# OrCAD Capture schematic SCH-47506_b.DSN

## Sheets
1 1. Title Page: title: 47506-X-BPMS-SHIELD-BOARD; rev: X1; company: NXP Semiconductors; note: SCH47506, SPF47506
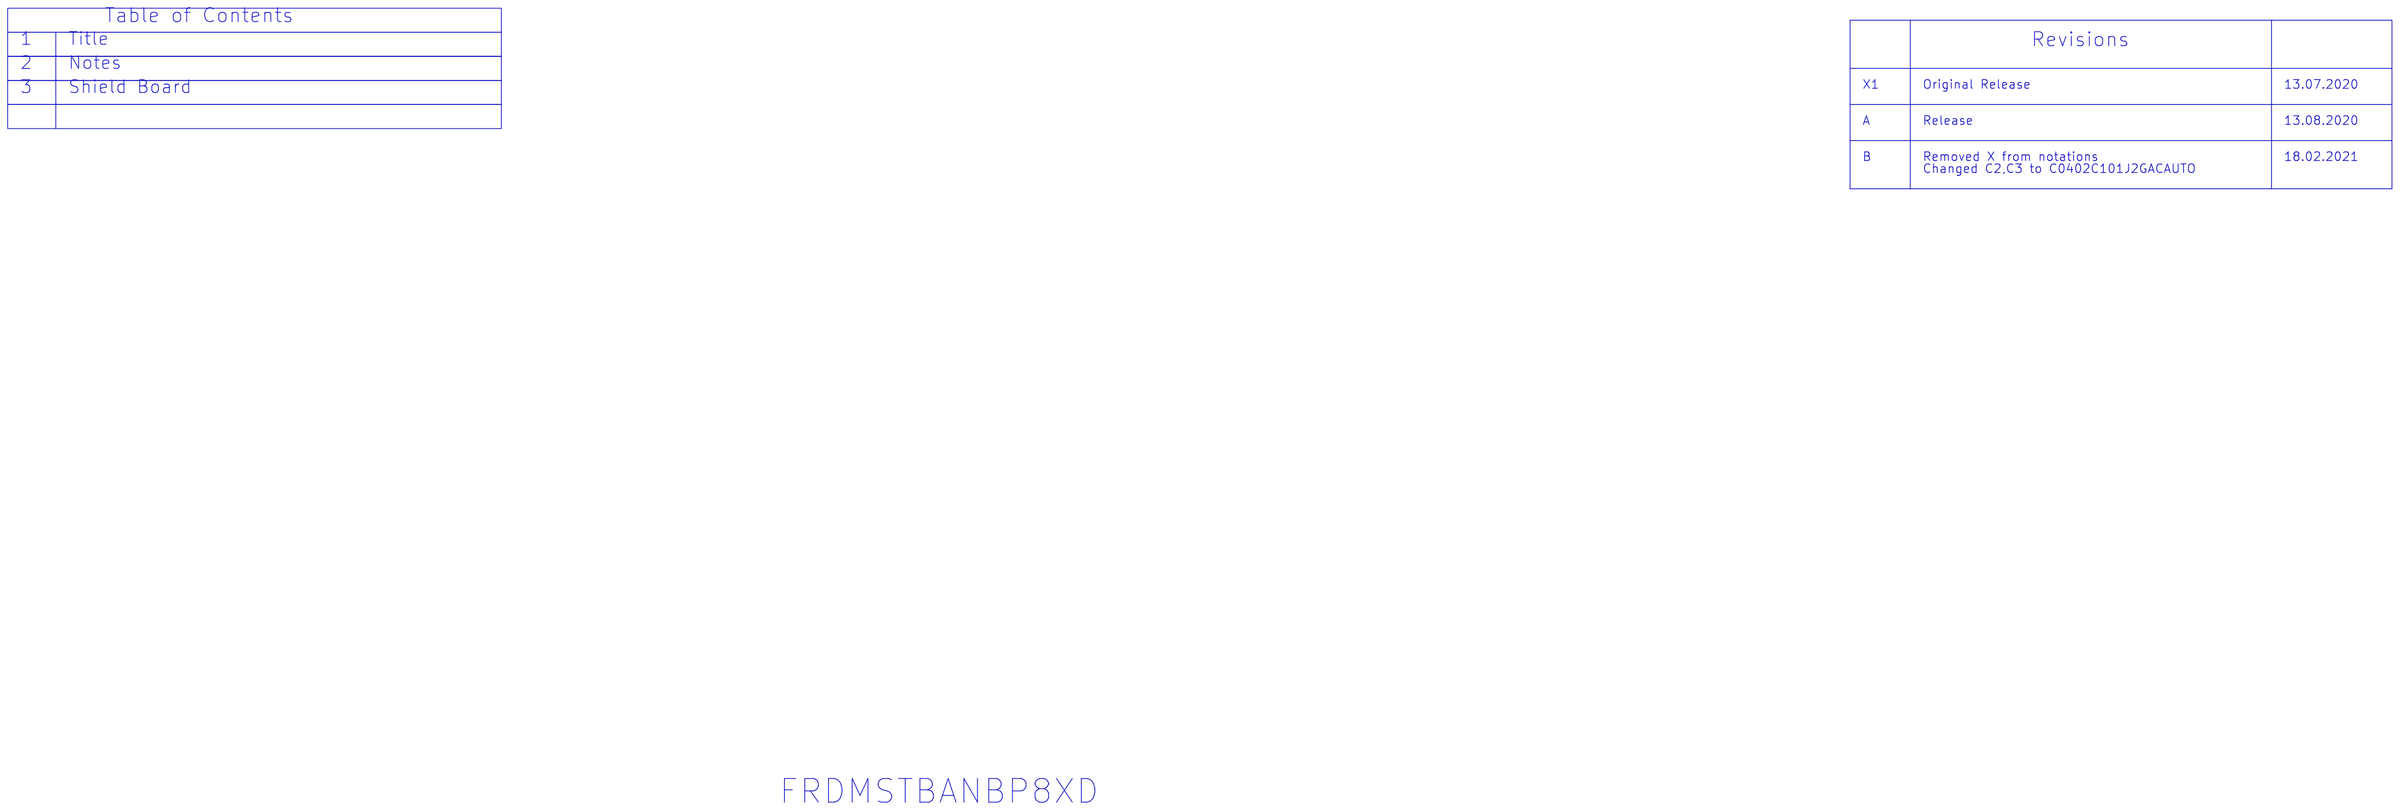
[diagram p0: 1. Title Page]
2 2. Notes
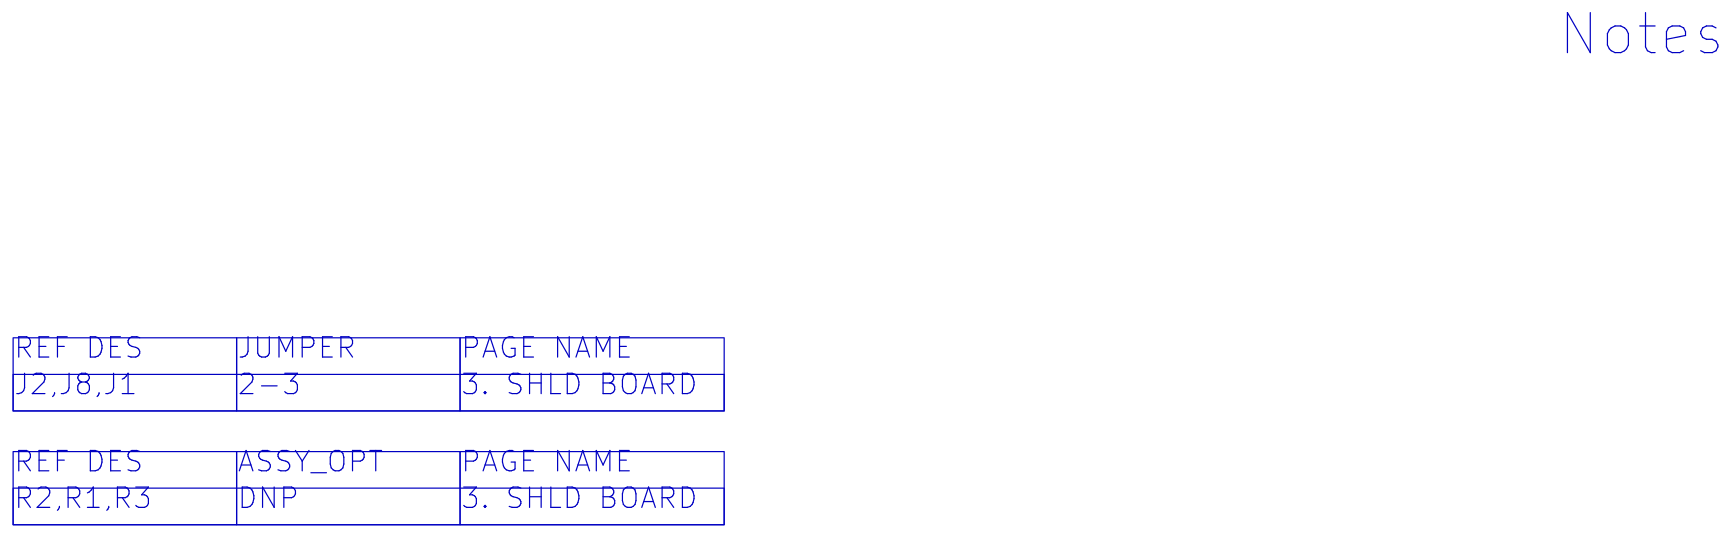
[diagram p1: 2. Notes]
3 3. SHLD BOARD: size C
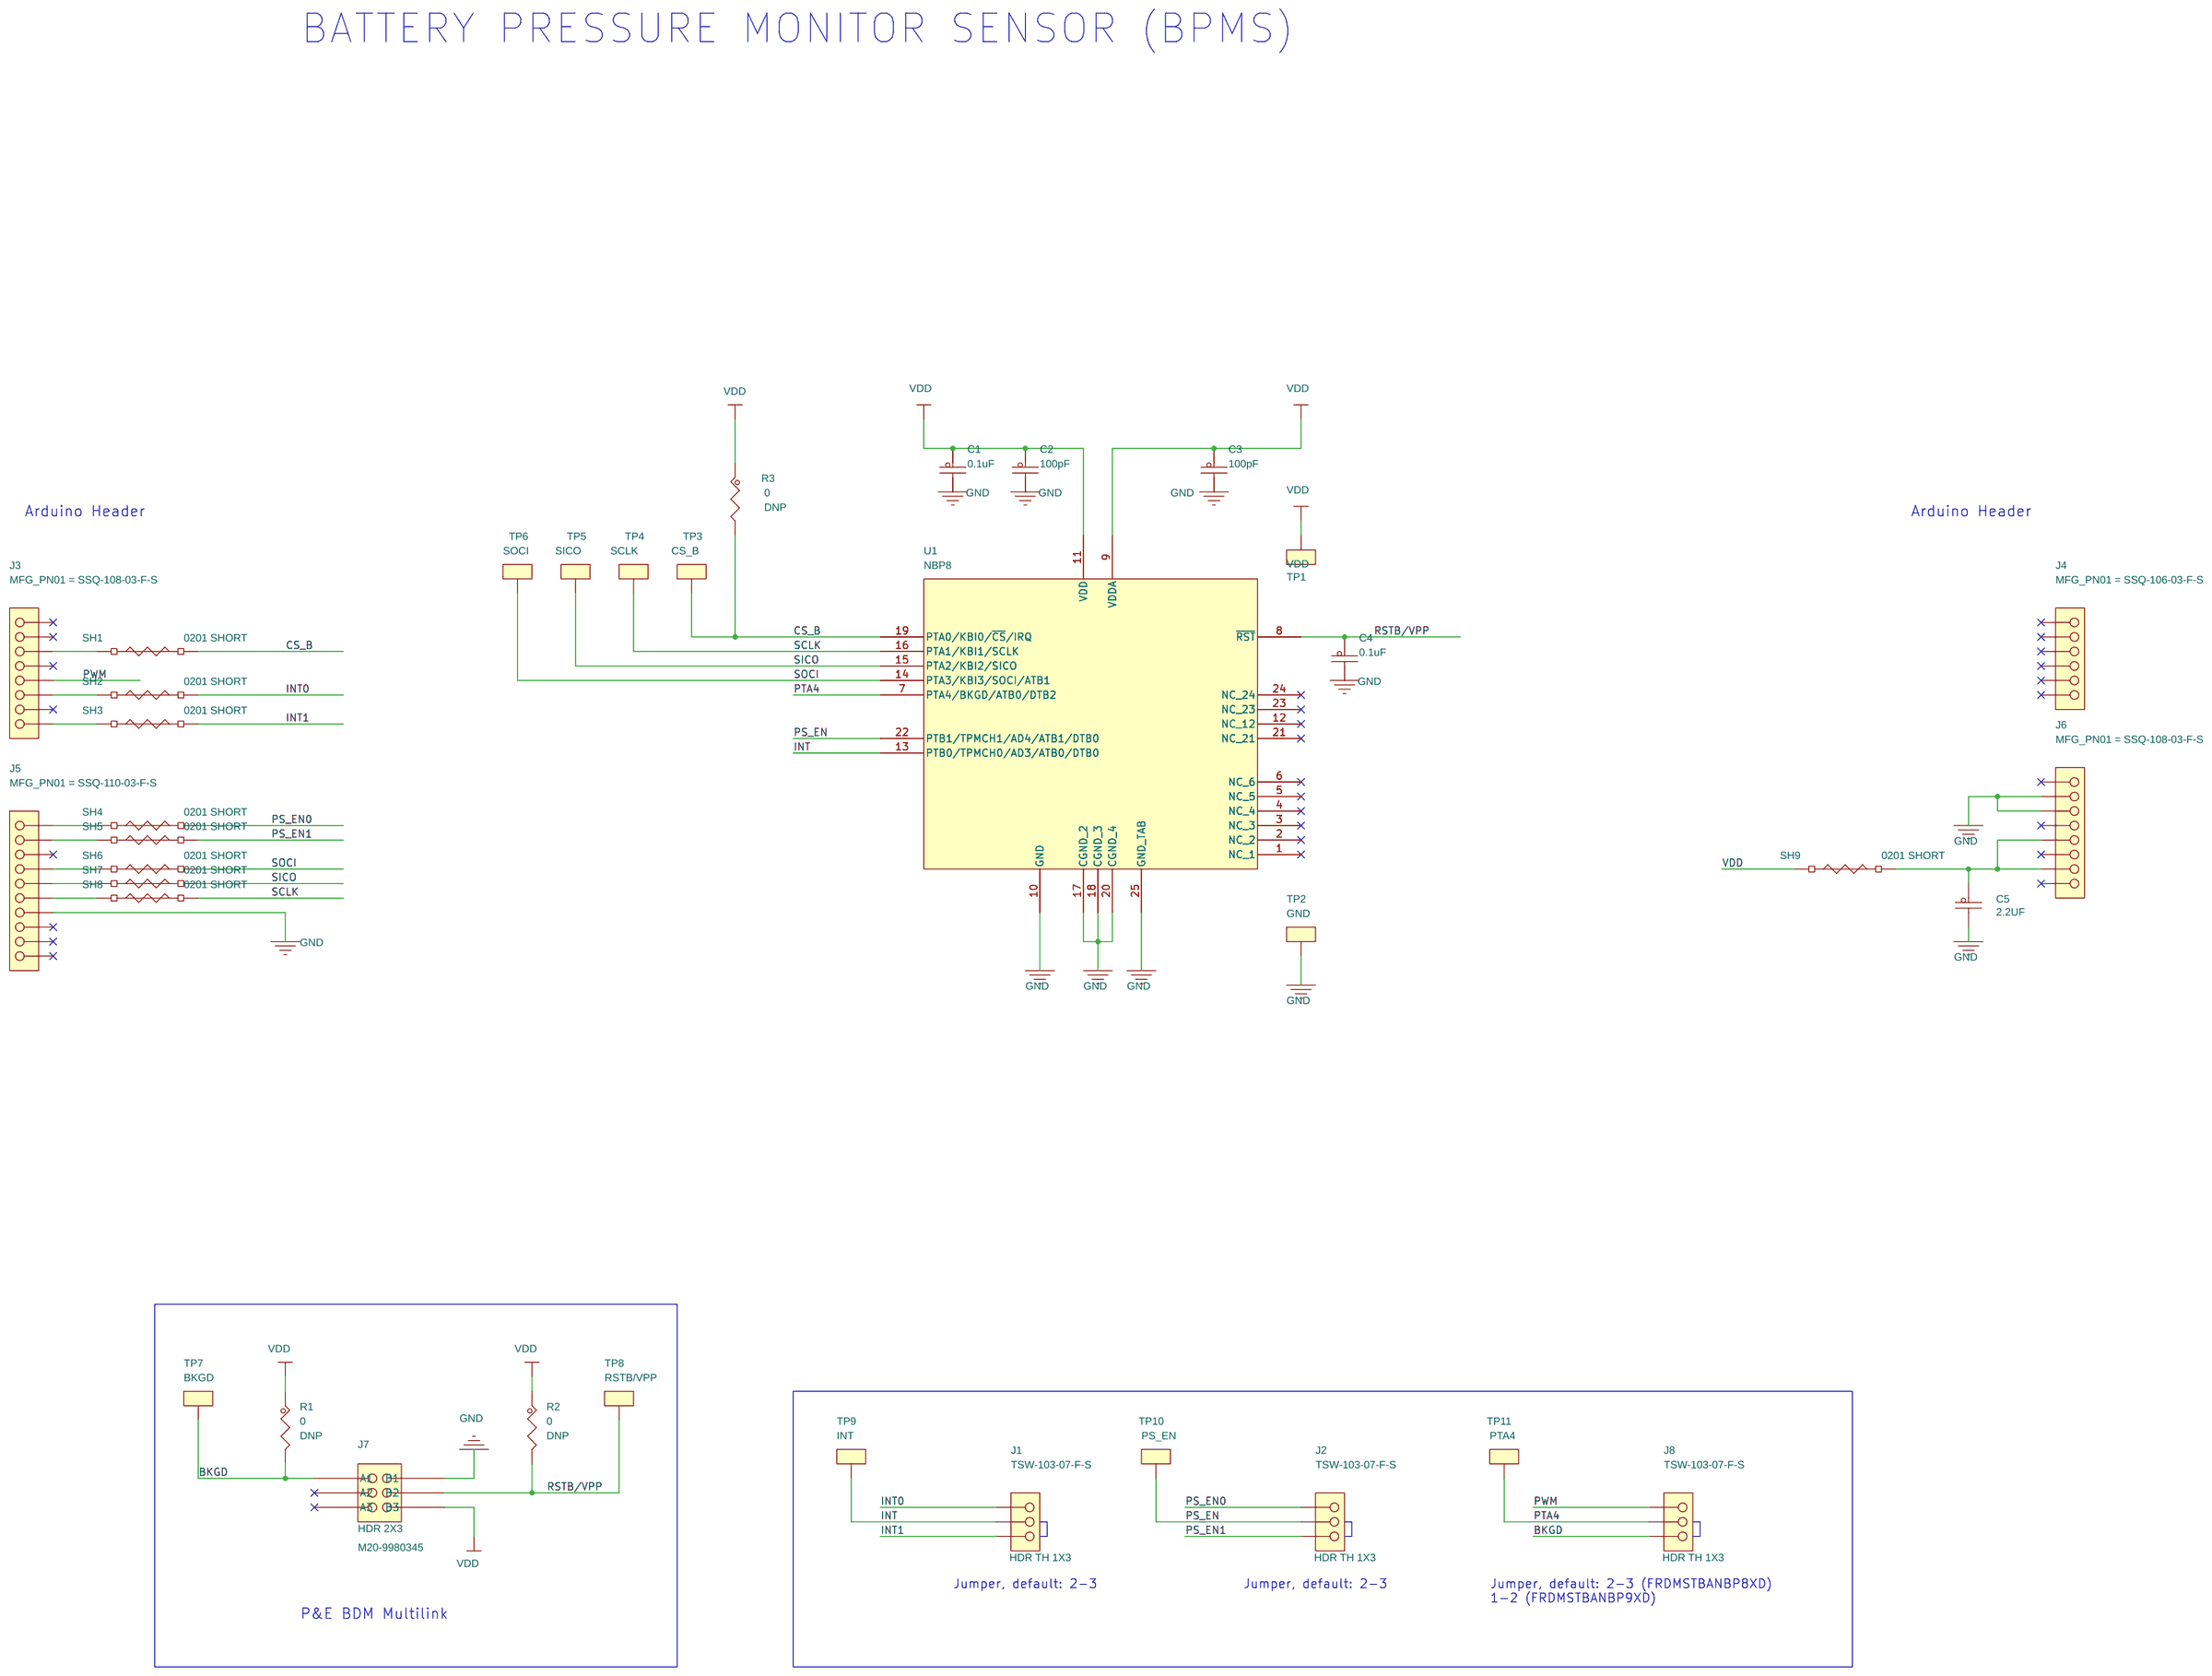
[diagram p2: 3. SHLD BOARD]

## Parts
C1  0.1uF  [CC0402_25]
C2  100pF  [CC0402_25]
C3  100pF  [CC0402_25]
C4  0.1uF  [CC0402_25]
C5  2.2UF  [CC0402_25]
J1  HDR TH 1X3  [HDR103]
J2  HDR TH 1X3  [HDR103]
J3  SKT_1X8  [con_skt1x8_th]
J4  SKT_1X6  [con_skt1x6_th]
J5  SKT_1X10  [con_skt1x10_th]
J6  SKT_1X8  [con_skt1x8_th]
J7  HDR 2X3  [hdr203_m20]
J8  HDR TH 1X3  [HDR103]
R1  0  [RC0402_25]
R2  0  [RC0402_25]
R3  0  [RC0402_25]
SH1  0201 SHORT  [0201_solder_blob_jumper_short]
SH2  0201 SHORT  [0201_solder_blob_jumper_short]
SH3  0201 SHORT  [0201_solder_blob_jumper_short]
SH4  0201 SHORT  [0201_solder_blob_jumper_short]
SH5  0201 SHORT  [0201_solder_blob_jumper_short]
SH6  0201 SHORT  [0201_solder_blob_jumper_short]
SH7  0201 SHORT  [0201_solder_blob_jumper_short]
SH8  0201 SHORT  [0201_solder_blob_jumper_short]
SH9  0201 SHORT  [0201_solder_blob_jumper_short]
TP1  0805  [testpoint_122x049mil]
TP2  0805  [testpoint_122x049mil]
TP3  0805  [testpoint_122x049mil]
TP4  0805  [testpoint_122x049mil]
TP5  0805  [testpoint_122x049mil]
TP6  0805  [testpoint_122x049mil]
TP7  0805  [testpoint_122x049mil]
TP8  0805  [testpoint_122x049mil]
TP9  0805  [testpoint_122x049mil]
TP10  0805  [testpoint_122x049mil]
TP11  0805  [testpoint_122x049mil]
U1  NBP8  [hpqfn24_0p5_4x4_ep_nsp]

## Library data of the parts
C1 C4 = CAP_NP: CAP CER 0.1uF 6.3V 10% X7R 0402; AGILE_PN: 150-78678; CAD_APPROVED: Yes; FPLIST: CC0402_25,CC0402_HD,0402_CC; HEIGHT: 0.55MM; MFG_NAME01: KEMET; MFG_PN01: C0402C104K9RACTU; Package Size: 0402; Package Type: Tape & reel; ROHS: Yes; TOL: 10%; Tolerance: 10%; VOLTAGE: 6.3V
C2 C3 = CAP_NP: CAP CER 100PF 200V 5% C0G AEC-Q200 0402; 3D_Mechanical_Footprint_File: ftp://fcl.am.freescale.net/ALLEGRO/step/cc0402_25.STEP; AGILE_PN: TMP-CIP-7231; CAD_APPROVED: Yes; FPLIST: CC0402_25,CC0402_HD,0402_CC,capc0402_l; HEIGHT: 0.55MM; MFG_NAME01: KEMET; MFG_PN01: C0402C101J2GACAUTO; PRE_APN: 150-81274; Package Size: 0402 (1005 Metric); Package Type: Surface Mount, MLCC; ROHS: Yes; Rated Voltage: 200V; Temp Range: -55 °C ~ 125 °C; Tolerance: 5%; VOLTAGE: 200V
C5 = CAP_NP: CAP CER 2.2UF 6.3V 20% X5R 0402; AGILE_PN: 150-76792; CAD_APPROVED: Yes; FPLIST: CC0402_25,CC0402_HD,0402_CC; HEIGHT: 0.55MM; MFG_NAME01: KEMET; MFG_PN01: C0402C225M9PACTU; Package Size: 0402; ROHS: Yes; Tolerance: 20%; VOLTAGE: 6.3V
J1 J2 J8 = CONN_HDR_3X1: HDR 1x3 TH 100MIL SP 343H AU 100L; AGILE_PN: 210-80734; CAD_APPROVED: Yes; HEIGHT: 8.72MM; Jumper: 2-3; MFG_NAME01: SAMTEC; MFG_PN01: TSW-103-07-F-S; ROHS: Yes
J3 J6 = CONN_HDR_8X1: CON 1X8 SKT TH 100MIL SP 340H AU 394L; 3D_Mechanical_Footprint_File: ftp://fcl.am.freescale.net/ALLEGRO/step/con_skt1x8_th_394l.STEP; AGILE_PN: 210-80359; CAD_APPROVED: Yes; HEIGHT: 8.64MM; MFG_NAME01: SAMTEC; MFG_PN01: SSQ-108-03-F-S; ROHS: Yes; Temp Range: -55°C to +125°C
J4 = CONN_HDR_6X1: CON 1X6 SKT TH 100MIL SP 340H AU 394L; AGILE_PN: 210-80357; CAD_APPROVED: Yes; HEIGHT: 8.64MM; MFG_NAME01: SAMTEC; MFG_PN01: SSQ-106-03-F-S; ROHS: Yes
J5 = CONN_HDR_10X1: CON 1X10 SKT TH 100MIL SP 340H AU 394L; 3D_Mechanical_Footprint_File: ftp://fcl.am.freescale.net/ALLEGRO/step/con_skt1x10_th_394l.STEP; AGILE_PN: 210-80360; CAD_APPROVED: Yes; HEIGHT: 8.64MM; MFG_NAME01: SAMTEC; MFG_PN01: SSQ-110-03-F-S; ROHS: Yes; Temp Range: -55°C to +125°C
J7 = CONN_HDR_3X2: HDR 2X3 TH 2.54MM SP 340H AU 118L; 3D_Mechanical_Footprint_File: ftp://fcl.am.freescale.net/ALLEGRO/step/hdr203_m20.STEP; AGILE_PN: 210-77295; CAD_APPROVED: Yes; HEIGHT: 8.64MM; MFG_NAME01: HARWIN INC; MFG_PN01: M20-9980345; ROHS: Yes
R1-R3 = RES: RES TF ZERO  OHM 1/16W AEC-Q200 RC0402; AGILE_PN: 470-75366; ASSY_OPT: DNP; CAD_APPROVED: Yes; FPLIST: RC0402_25,RC0402_HD,0402_CC; HEIGHT: 0.35mm; MFG_NAME01: VISHAY INTERTECHNOLOGY; MFG_PN01: CRCW04020000ZS; ROHS: Yes; TOL: 5%; Tolerance: 5%
SH1-SH9 = RES_SHORT-2: SOLDER BLOB 0201 SHORT - NO PART TO ORDER; AGILE_PN: 470-81068; CAD_APPROVED: Yes; FPLIST: 0201_solder_blob_jumper_short,0201_solder_blob_jumper_short_a; HEIGHT: 0.1MM; MFG_NAME01: NA; MFG_PN01: NO PART TO ORDER1; ROHS: Yes
TP1 = TEST_POINT: TEST POINT PAD 3.1MMX1.25MM SMT AEC-Q200 0805; AGILE_PN: 211-79608; CAD_APPROVED: Yes; HEIGHT: 1.45MM; MFG_NAME01: KOA SPEER; MFG_PN01: RCTCTE; Package Size: 2X1.25x1.45MM; Package Type: SMT; ROHS: Yes; SILK: VDD
TP2 = TEST_POINT: TEST POINT PAD 3.1MMX1.25MM SMT AEC-Q200 0805; AGILE_PN: 211-79608; CAD_APPROVED: Yes; HEIGHT: 1.45MM; MFG_NAME01: KOA SPEER; MFG_PN01: RCTCTE; Package Size: 2X1.25x1.45MM; Package Type: SMT; ROHS: Yes; SILK: GND
TP3 = TEST_POINT: TEST POINT PAD 3.1MMX1.25MM SMT AEC-Q200 0805; AGILE_PN: 211-79608; CAD_APPROVED: Yes; HEIGHT: 1.45MM; MFG_NAME01: KOA SPEER; MFG_PN01: RCTCTE; Package Size: 2X1.25x1.45MM; Package Type: SMT; ROHS: Yes; SILK: CS_B
TP4 = TEST_POINT: TEST POINT PAD 3.1MMX1.25MM SMT AEC-Q200 0805; AGILE_PN: 211-79608; CAD_APPROVED: Yes; HEIGHT: 1.45MM; MFG_NAME01: KOA SPEER; MFG_PN01: RCTCTE; Package Size: 2X1.25x1.45MM; Package Type: SMT; ROHS: Yes; SILK: SCLK
TP5 = TEST_POINT: TEST POINT PAD 3.1MMX1.25MM SMT AEC-Q200 0805; AGILE_PN: 211-79608; CAD_APPROVED: Yes; HEIGHT: 1.45MM; MFG_NAME01: KOA SPEER; MFG_PN01: RCTCTE; Package Size: 2X1.25x1.45MM; Package Type: SMT; ROHS: Yes; SILK: SICO
TP6 = TEST_POINT: TEST POINT PAD 3.1MMX1.25MM SMT AEC-Q200 0805; AGILE_PN: 211-79608; CAD_APPROVED: Yes; HEIGHT: 1.45MM; MFG_NAME01: KOA SPEER; MFG_PN01: RCTCTE; Package Size: 2X1.25x1.45MM; Package Type: SMT; ROHS: Yes; SILK: SOCI
TP7 = TEST_POINT: TEST POINT PAD 3.1MMX1.25MM SMT AEC-Q200 0805; AGILE_PN: 211-79608; CAD_APPROVED: Yes; HEIGHT: 1.45MM; MFG_NAME01: KOA SPEER; MFG_PN01: RCTCTE; Package Size: 2X1.25x1.45MM; Package Type: SMT; ROHS: Yes; SILK: BKGD
TP8 = TEST_POINT: TEST POINT PAD 3.1MMX1.25MM SMT AEC-Q200 0805; AGILE_PN: 211-79608; CAD_APPROVED: Yes; HEIGHT: 1.45MM; MFG_NAME01: KOA SPEER; MFG_PN01: RCTCTE; Package Size: 2X1.25x1.45MM; Package Type: SMT; ROHS: Yes; SILK: RSTB/VPP
TP9 = TEST_POINT: TEST POINT PAD 3.1MMX1.25MM SMT AEC-Q200 0805; AGILE_PN: 211-79608; CAD_APPROVED: Yes; HEIGHT: 1.45MM; MFG_NAME01: KOA SPEER; MFG_PN01: RCTCTE; Package Size: 2X1.25x1.45MM; Package Type: SMT; ROHS: Yes; SILK: INT
TP10 = TEST_POINT: TEST POINT PAD 3.1MMX1.25MM SMT AEC-Q200 0805; AGILE_PN: 211-79608; CAD_APPROVED: Yes; HEIGHT: 1.45MM; MFG_NAME01: KOA SPEER; MFG_PN01: RCTCTE; Package Size: 2X1.25x1.45MM; Package Type: SMT; ROHS: Yes; SILK: PS_EN
TP11 = TEST_POINT: TEST POINT PAD 3.1MMX1.25MM SMT AEC-Q200 0805; AGILE_PN: 211-79608; CAD_APPROVED: Yes; HEIGHT: 1.45MM; MFG_NAME01: KOA SPEER; MFG_PN01: RCTCTE; Package Size: 2X1.25x1.45MM; Package Type: SMT; ROHS: Yes; SILK: PTA4
U1 = NBP8_HQFN24P_4_ALT-NSP: IC BATTERY PRESSURE MONITOR SENSOR BPMS 3.8V AEC-Q100 HQFN24; 3D_Mechanical_Footprint_File: ftp://fcl.am.freescale.net/ALLEGRO/step/hpqfn24_0p5_4x4_ep.STEP; AGILE_PN: TMP-CIP-5570; CAD_APPROVED: Yes; FPLIST: hpqfn24_0p5_4x4_ep,hpqfn24_0p5_4x4_ep_nsp; HEIGHT: 2.08 MM; MFG_NAME01: NXP SEMICONDUCTORS; MFG_PN01: NBP8FD; PRE_APN: 312-82985; ROHS: Yes; Temp Range: -40  °C to +85 °C

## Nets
GND: C1.2 C2.2 C3.2 C4.2 C5.2 J5.7 J6.6 J6.7 J7.2(B1) TP2.1 U1.10(GND) U1.17(CGND_2) U1.18(CGND_3) U1.20(CGND_4) U1.25(GND_TAB)
VDD: C1.1 C2.1 C3.1 J7.6(B3) R1.1 R2.1 R3.1 SH9.1 TP1.1 U1.9(VDDA) U1.11(VDD)
BKGD: J7.1(A1) J8.3 R1.2 TP7.1
CS_B: R3.2 SH1.2 TP3.1 U1.19(PTA0/KBI0/~{CS}/IRQ)
INT: J1.2 TP9.1 U1.13(PTB0/TPMCH0/AD3/ATB0/DTB0)
INT0: J1.1 SH2.2
INT1: J1.3 SH3.2
PS_EN: J2.2 TP10.1 U1.22(PTB1/TPMCH1/AD4/ATB1/DTB0)
PS_EN0: J2.1 SH4.2
PS_EN1: J2.3 SH5.2
PTA4: J8.2 TP11.1 U1.7(PTA4/BKGD/ATB0/DTB2)
PWM: J3.5 J8.1
RSTB/VPP: C4.1 J7.4(B2) R2.2 TP8.1 U1.8(~{RST})
SCLK: SH8.2 TP4.1 U1.16(PTA1/KBI1/SCLK)
SICO: SH7.2 TP5.1 U1.15(PTA2/KBI2/SICO)
SOCI: SH6.2 TP6.1 U1.14(PTA3/KBI3/SOCI/ATB1)
N16645673: C5.1 J6.2 J6.4 SH9.2
N16648755: J3.3 SH1.1
N16660945: J5.4 SH6.1
N16660985: J5.5 SH7.1
N16661025: J5.6 SH8.1
N16669684: J3.8 SH3.1
N16670698: J5.1 SH4.1
N16670702: J5.2 SH5.1
N16670795: J3.6 SH2.1

Not connected (* = marked no-connect by the designer): J3 1* 2* 4* 7*; J4 1* 2* 3* 4* 5* 6*; J5 3* 8* 9* 10*; J6 1* 3* 5* 8*; J7 3(A2)* 5(A3)*; U1 1(NC)* 2(NC)* 3(NC)* 4(NC)* 5(NC)* 6(NC)* 12(NC)* 21(NC)* 23(NC)* 24(NC)*

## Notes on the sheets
sheet 1
- Table of Contents
- 1
- Title
- Revisions
- 2
- Notes
- 3
- Shield Board
- X1
- Original Release
- 13.07.2020
- A
- Release
- 13.08.2020
- B
- Removed X from notations
- 18.02.2021
- Changed C2,C3 to C0402C101J2GACAUTO
- FRDMSTBANBP8XD
sheet 2
- Notes
- REF DES
- JUMPER
- PAGE NAME
- J2,J8,J1
- 2-3
- 3. SHLD BOARD
- REF DES
- ASSY_OPT
- PAGE NAME
- R2,R1,R3
- DNP
- 3. SHLD BOARD
sheet 3
- BATTERY PRESSURE MONITOR SENSOR (BPMS)
- Arduino Header
- Arduino Header
- Jumper, default: 2-3
- Jumper, default: 2-3
- Jumper, default: 2-3 (FRDMSTBANBP8XD)
  1-2 (FRDMSTBANBP9XD)
- P&E BDM Multilink
